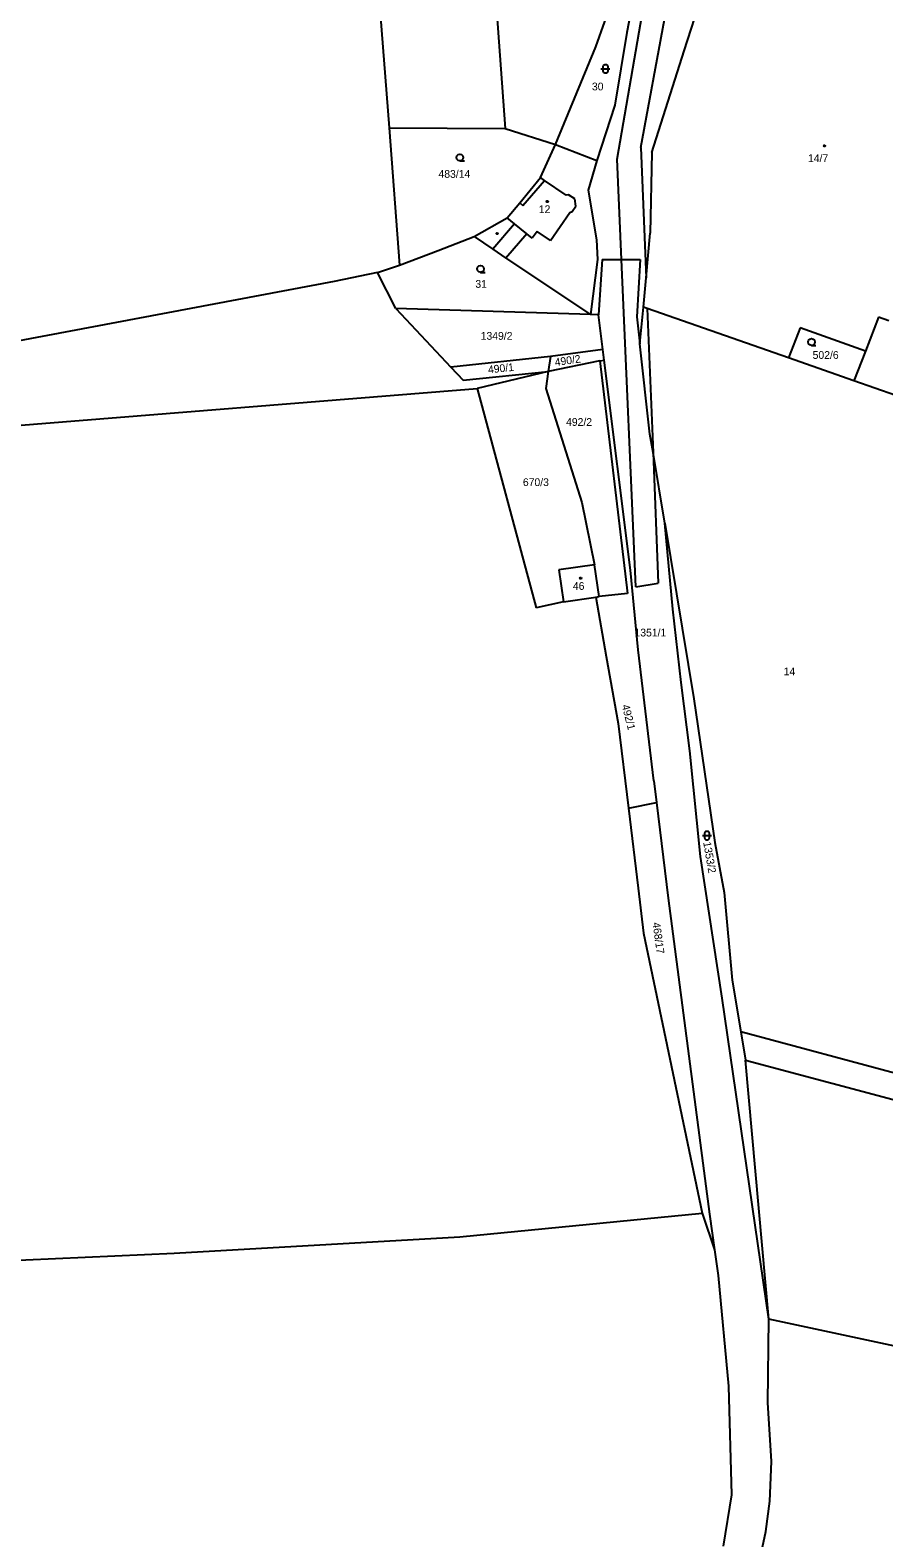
# Model space of a CAD drawing. Extents: x -852001 to -842497, y -1063614 to -1052182.
# Drawn here: x -844799.8 to -844613.1, y -1061856 to -1061526.1 of the extents above; entities that cross this region are included whole.
import ezdxf

# ---------------------------------------------------------------- set-up
doc = ezdxf.new("R2010")
doc.units = 0
for name, color, linetype in [('Default', 7, 'Continuous'), ('KN_HRANICE', 7, 'Continuous'), ('KN_KULTURY', 7, 'Continuous'), ('KN_PARCELY', 7, 'Continuous'), ('KN_SLUCKY', 7, 'Continuous')]:
    doc.layers.add(name, color=color, linetype=linetype)

# ---------------------------------------------------------------- blocks, each defined once
blk = doc.blocks.new('304')
at = {"layer": 'Default'}
blk.add_lwpolyline([(0, 0), (-0.38, 0.1), (-0.65, 0.37), (-0.75, 0.74), (-0.65, 1.11), (-0.38, 1.38), (-0.01, 1.48), (0.36, 1.38), (0.63, 1.11), (0.73, 0.73), (0.63, 0.35), (0.36, 0.08), (-0.02, -0.02), (0.98, -0.02)], dxfattribs=at)
blk = doc.blocks.new('316')
at = {"layer": 'Default'}
for points in [[(-1, 1), (0.27, 1), (1, 1)], [(-0.5, 1.5), (-0.4, 1.79), (-0.15, 1.97), (0.16, 1.97), (0.41, 1.79), (0.51, 1.5), (0.51, 0.5), (0.41, 0.21), (0.16, 0.03), (-0.15, 0.03), (-0.4, 0.21), (-0.5, 0.5), (-0.5, 1.5)]]:
    blk.add_lwpolyline(points, dxfattribs=at)
blk = doc.blocks.new('NAHRADNI_SYMBOL')
at = {"layer": 'Default'}
blk.add_lwpolyline([(0.09, 0.15), (0.18, 0), (0.09, -0.15), (-0.09, -0.15), (-0.18, 0), (-0.09, 0.15), (0.09, 0.15)], dxfattribs=at)
blk = doc.blocks.new('402')
at = {"layer": 'Default'}
blk.add_lwpolyline([(0.09, 0.15), (0.18, 0), (0.09, -0.15), (-0.09, -0.15), (-0.18, 0), (-0.09, 0.15), (0.09, 0.15)], dxfattribs=at)

msp = doc.modelspace()

# ---------------------------------------------------------------- linework, layer by layer
at = {"layer": 'KN_HRANICE'}
for p, q in [((-844700.84, -1061479.9), (-844695.93, -1061547.63)), ((-844726.14, -1061484.58), (-844721.31, -1061547.47)), ((-844676.11, -1061529.78), (-844669.25, -1061510.34)), ((-844656.75, -1061530.65), (-844650.67, -1061511.68)), ((-844667, -1061514.65), (-844669.29, -1061526.62)), ((-844669.29, -1061526.62), (-844671.98, -1061542.55)), ((-844684.89, -1061551.1), (-844676.11, -1061529.78)), ((-844663.88, -1061552.91), (-844656.75, -1061530.65)), ((-844671.98, -1061542.55), (-844675.88, -1061554.66)), ((-844721.31, -1061547.47), (-844719.04, -1061577.54)), ((-844721.31, -1061547.47), (-844695.93, -1061547.63)), ((-844695.93, -1061547.63), (-844684.89, -1061551.1)), ((-844688.22, -1061558.36), (-844684.89, -1061551.1)), ((-844684.89, -1061551.1), (-844675.88, -1061554.66)), ((-844663.88, -1061552.91), (-844664.2, -1061570.52)), ((-844675.88, -1061554.66), (-844677.76, -1061561.12)), ((-844692.75, -1061563.86), (-844688.22, -1061558.36)), ((-844677.76, -1061561.12), (-844675.98, -1061571.96)), ((-844695.51, -1061567.21), (-844692.75, -1061563.86)), ((-844702.71, -1061571.23), (-844695.51, -1061567.21)), ((-844710.57, -1061574.35), (-844702.71, -1061571.23)), ((-844702.71, -1061571.23), (-844698.65, -1061574.01)), ((-844675.98, -1061571.96), (-844675.77, -1061576.3)), ((-844665.12, -1061580.33), (-844664.2, -1061570.52)), ((-844719.04, -1061577.54), (-844710.57, -1061574.35)), ((-844698.65, -1061574.01), (-844695.79, -1061575.97)), ((-844695.79, -1061575.97), (-844677.25, -1061588.3)), ((-844675.77, -1061576.3), (-844677.25, -1061588.3)), ((-844674.74, -1061576.3), (-844675.5, -1061588.38)), ((-844674.74, -1061576.3), (-844670.48, -1061576.3)), ((-844670.48, -1061576.3), (-844666.43, -1061576.3)), ((-844666.43, -1061576.3), (-844667.1, -1061588.8)), ((-844723.83, -1061579.1), (-844733.32, -1061581.08)), ((-844723.83, -1061579.1), (-844719.04, -1061577.54)), ((-844719.87, -1061587.02), (-844723.83, -1061579.1)), ((-844733.32, -1061581.08), (-844847.74, -1061602.71)), ((-844665.71, -1061586.69), (-844665.12, -1061580.33)), ((-844677.25, -1061588.3), (-844719.87, -1061587.02)), ((-844719.87, -1061587.02), (-844707.78, -1061599.88)), ((-844675.5, -1061588.38), (-844677.25, -1061588.3)), ((-844674.55, -1061596.01), (-844675.5, -1061588.38)), ((-844667.1, -1061588.8), (-844666.46, -1061594.72)), ((-844666.46, -1061594.72), (-844665.71, -1061586.69)), ((-844664.85, -1061586.99), (-844665.71, -1061586.69)), ((-844633.94, -1061597.82), (-844664.85, -1061586.99)), ((-844614.25, -1061588.91), (-844617.15, -1061596.33)), ((-844611.99, -1061589.68), (-844614.25, -1061588.91)), ((-844631.41, -1061591.24), (-844633.94, -1061597.82)), ((-844617.15, -1061596.33), (-844631.41, -1061591.24)), ((-844674.55, -1061596.01), (-844686.03, -1061597.5)), ((-844674.27, -1061598.28), (-844674.55, -1061596.01)), ((-844664.26, -1061614.5), (-844666.46, -1061594.72)), ((-844617.15, -1061596.33), (-844619.71, -1061602.81)), ((-844686.03, -1061597.5), (-844707.78, -1061599.88)), ((-844686.03, -1061597.5), (-844686.52, -1061600.77)), ((-844675.23, -1061598.44), (-844686.52, -1061600.77)), ((-844675.23, -1061598.44), (-844674.27, -1061598.28)), ((-844675.23, -1061598.44), (-844669.19, -1061649.38)), ((-844668.53, -1061644.27), (-844674.27, -1061598.28)), ((-844619.71, -1061602.81), (-844633.94, -1061597.82)), ((-844707.78, -1061599.88), (-844705.14, -1061602.69)), ((-844705.14, -1061602.69), (-844686.52, -1061600.77)), ((-844686.52, -1061600.77), (-844702.03, -1061604.51)), ((-844686.52, -1061600.77), (-844687, -1061604.52)), ((-844610.46, -1061606.05), (-844619.71, -1061602.81)), ((-844847.67, -1061616.18), (-844702.03, -1061604.51)), ((-844702.03, -1061604.51), (-844689.16, -1061652.49)), ((-844687, -1061604.52), (-844679.16, -1061629.46)), ((-844663.59, -1061618.53), (-844664.26, -1061614.5)), ((-844661.03, -1061633.98), (-844663.59, -1061618.53)), ((-844679.16, -1061629.46), (-844676.42, -1061643.1)), ((-844659.25, -1061652.78), (-844661.03, -1061633.98)), ((-844661.03, -1061633.98), (-844654.65, -1061672.42)), ((-844676.42, -1061643.1), (-844684.16, -1061644.22)), ((-844684.16, -1061644.22), (-844683.15, -1061651.22)), ((-844675.39, -1061650.03), (-844676.42, -1061643.1)), ((-844666.82, -1061661.66), (-844668.53, -1061644.27)), ((-844683.15, -1061651.22), (-844689.16, -1061652.49)), ((-844683.15, -1061651.22), (-844676.12, -1061650.14)), ((-844676.12, -1061650.14), (-844675.39, -1061650.03)), ((-844676.12, -1061650.14), (-844673.84, -1061663.14)), ((-844669.19, -1061649.38), (-844675.39, -1061650.03)), ((-844657.47, -1061668.83), (-844659.25, -1061652.78)), ((-844663.4, -1061690.33), (-844666.82, -1061661.66)), ((-844673.84, -1061663.14), (-844671.23, -1061677.79)), ((-844655.52, -1061683.8), (-844657.47, -1061668.83)), ((-844654.65, -1061672.42), (-844650.1, -1061703.82)), ((-844671.23, -1061677.79), (-844668.97, -1061696.33)), ((-844653.23, -1061706.89), (-844655.52, -1061683.8)), ((-844663.4, -1061690.33), (-844662.82, -1061695.12)), ((-844668.97, -1061696.33), (-844662.82, -1061695.12)), ((-844662.82, -1061695.12), (-844660.29, -1061716.05)), ((-844668.97, -1061696.33), (-844666.83, -1061713.85)), ((-844650.1, -1061703.82), (-844648, -1061714.79)), ((-844648.49, -1061737.9), (-844653.23, -1061706.89)), ((-844666.83, -1061713.85), (-844665.69, -1061723.64)), ((-844648, -1061714.79), (-844646.27, -1061733.99)), ((-844660.29, -1061716.05), (-844651.27, -1061785.12)), ((-844665.69, -1061723.64), (-844652.84, -1061784.91)), ((-844646.27, -1061733.99), (-844644.38, -1061745.28)), ((-844638.27, -1061808.11), (-844648.49, -1061737.9)), ((-844608.61, -1061754.86), (-844644.38, -1061745.28)), ((-844644.38, -1061745.28), (-844643.35, -1061751.43)), ((-844643.35, -1061751.43), (-844548.2, -1061776.97)), ((-844638.27, -1061808.11), (-844643.35, -1061751.43)), ((-844705.85, -1061790.12), (-844652.84, -1061784.91)), ((-844652.84, -1061784.91), (-844652.8, -1061785.12)), ((-844652.8, -1061785.12), (-844650.14, -1061792.98)), ((-844651.27, -1061785.12), (-844650.14, -1061792.98)), ((-844768.3, -1061793.68), (-844705.85, -1061790.12)), ((-844828.09, -1061796.43), (-844768.3, -1061793.68)), ((-844650.14, -1061792.98), (-844649.34, -1061798.57)), ((-844649.34, -1061798.57), (-844647.09, -1061822.8)), ((-844638.48, -1061826.34), (-844638.27, -1061808.11)), ((-844561.98, -1061824.56), (-844638.27, -1061808.11)), ((-844647.09, -1061822.8), (-844646.44, -1061846.57)), ((-844637.72, -1061839.25), (-844638.48, -1061826.34)), ((-844638.06, -1061847.91), (-844637.72, -1061839.25)), ((-844646.44, -1061846.57), (-844648.26, -1061857.77)), ((-844638.9, -1061854.57), (-844638.06, -1061847.91)), ((-844641.95, -1061868.66), (-844638.9, -1061854.57))]:
    msp.add_line(p, q, dxfattribs=at)
at = {"layer": 'KN_SLUCKY'}
for p, q in [((-844671.44, -1061554.37), (-844665.98, -1061522.69)), ((-844666.26, -1061551.77), (-844661.05, -1061523.77)), ((-844666.26, -1061551.77), (-844665.12, -1061580.33)), ((-844670.48, -1061576.3), (-844671.44, -1061554.37)), ((-844692.06, -1061564.45), (-844687.29, -1061558.98)), ((-844687.29, -1061558.98), (-844688.22, -1061558.36)), ((-844682.58, -1061562.2), (-844687.29, -1061558.98)), ((-844682.07, -1061562.17), (-844682.58, -1061562.2)), ((-844680.71, -1061563.03), (-844682.07, -1061562.17)), ((-844680.45, -1061564.59), (-844680.71, -1061563.03)), ((-844692.75, -1061563.86), (-844692.06, -1061564.45)), ((-844686.01, -1061572.15), (-844681.78, -1061566)), ((-844681.78, -1061566), (-844681.28, -1061565.81)), ((-844681.28, -1061565.81), (-844680.45, -1061564.59)), ((-844693.91, -1061568.47), (-844698.65, -1061574.01)), ((-844693.91, -1061568.47), (-844695.51, -1061567.21)), ((-844691.2, -1061570.69), (-844693.91, -1061568.47)), ((-844691.2, -1061570.69), (-844695.79, -1061575.97)), ((-844690.02, -1061571.62), (-844691.2, -1061570.69)), ((-844688.92, -1061570.18), (-844690.02, -1061571.62)), ((-844686.01, -1061572.15), (-844688.92, -1061570.18)), ((-844667.35, -1061647.89), (-844670.48, -1061576.3)), ((-844664.85, -1061586.99), (-844663.59, -1061618.53)), ((-844663.59, -1061618.53), (-844662.45, -1061647.1)), ((-844667.35, -1061647.89), (-844662.45, -1061647.1))]:
    msp.add_line(p, q, dxfattribs=at)

# ---------------------------------------------------------------- block references
at = {"layer": 'KN_KULTURY'}
for name, p in [('316', (-844674.01, -1061535.59)), ('304', (-844705.81, -1061554.7)), ('NAHRADNI_SYMBOL', (-844626.08, -1061551.43)), ('402', (-844686.71, -1061563.61)), ('402', (-844697.69, -1061570.61)), ('304', (-844701.3, -1061579.09)), ('304', (-844628.94, -1061595.08)), ('402', (-844679.4, -1061646)), ('316', (-844651.8, -1061703.33))]:
    msp.add_blockref(name, p, dxfattribs=at)

# ---------------------------------------------------------------- texts
at = {"layer": 'KN_PARCELY'}
for s, p in [('30', (-844676.95, -1061539.29)), ('14/7', (-844629.7, -1061554.97)), ('483/14', (-844710.51, -1061558.42)), ('12', (-844688.57, -1061566.14)), ('31', (-844702.44, -1061582.48)), ('1349/2', (-844701.28, -1061593.85)), ('502/6', (-844628.69, -1061598.03)), ('492/2', (-844682.61, -1061612.69)), ('670/3', (-844692.05, -1061625.86)), ('46', (-844681.12, -1061648.57)), ('1351/1', (-844667.64, -1061658.76)), ('14', (-844635.02, -1061667.26))]:
    msp.add_text(s, height=1.7, dxfattribs=at).set_placement(p)
for s, rotation, p in [('490/1', 5.844, (-844699.6, -1061601.23)), ('490/2', 8.193, (-844684.96, -1061599.62)), ('492/1', 284.302, (-844670.45, -1061673.87)), ('1353/2', 279.775, (-844652.63, -1061703.82)), ('468/17', 277.827, (-844663.71, -1061721.42))]:
    msp.add_text(s, height=1.7, rotation=rotation, dxfattribs=at).set_placement(p)

doc.saveas('drawing.dxf')
